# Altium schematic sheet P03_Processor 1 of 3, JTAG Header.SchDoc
size 513 x 386 mm
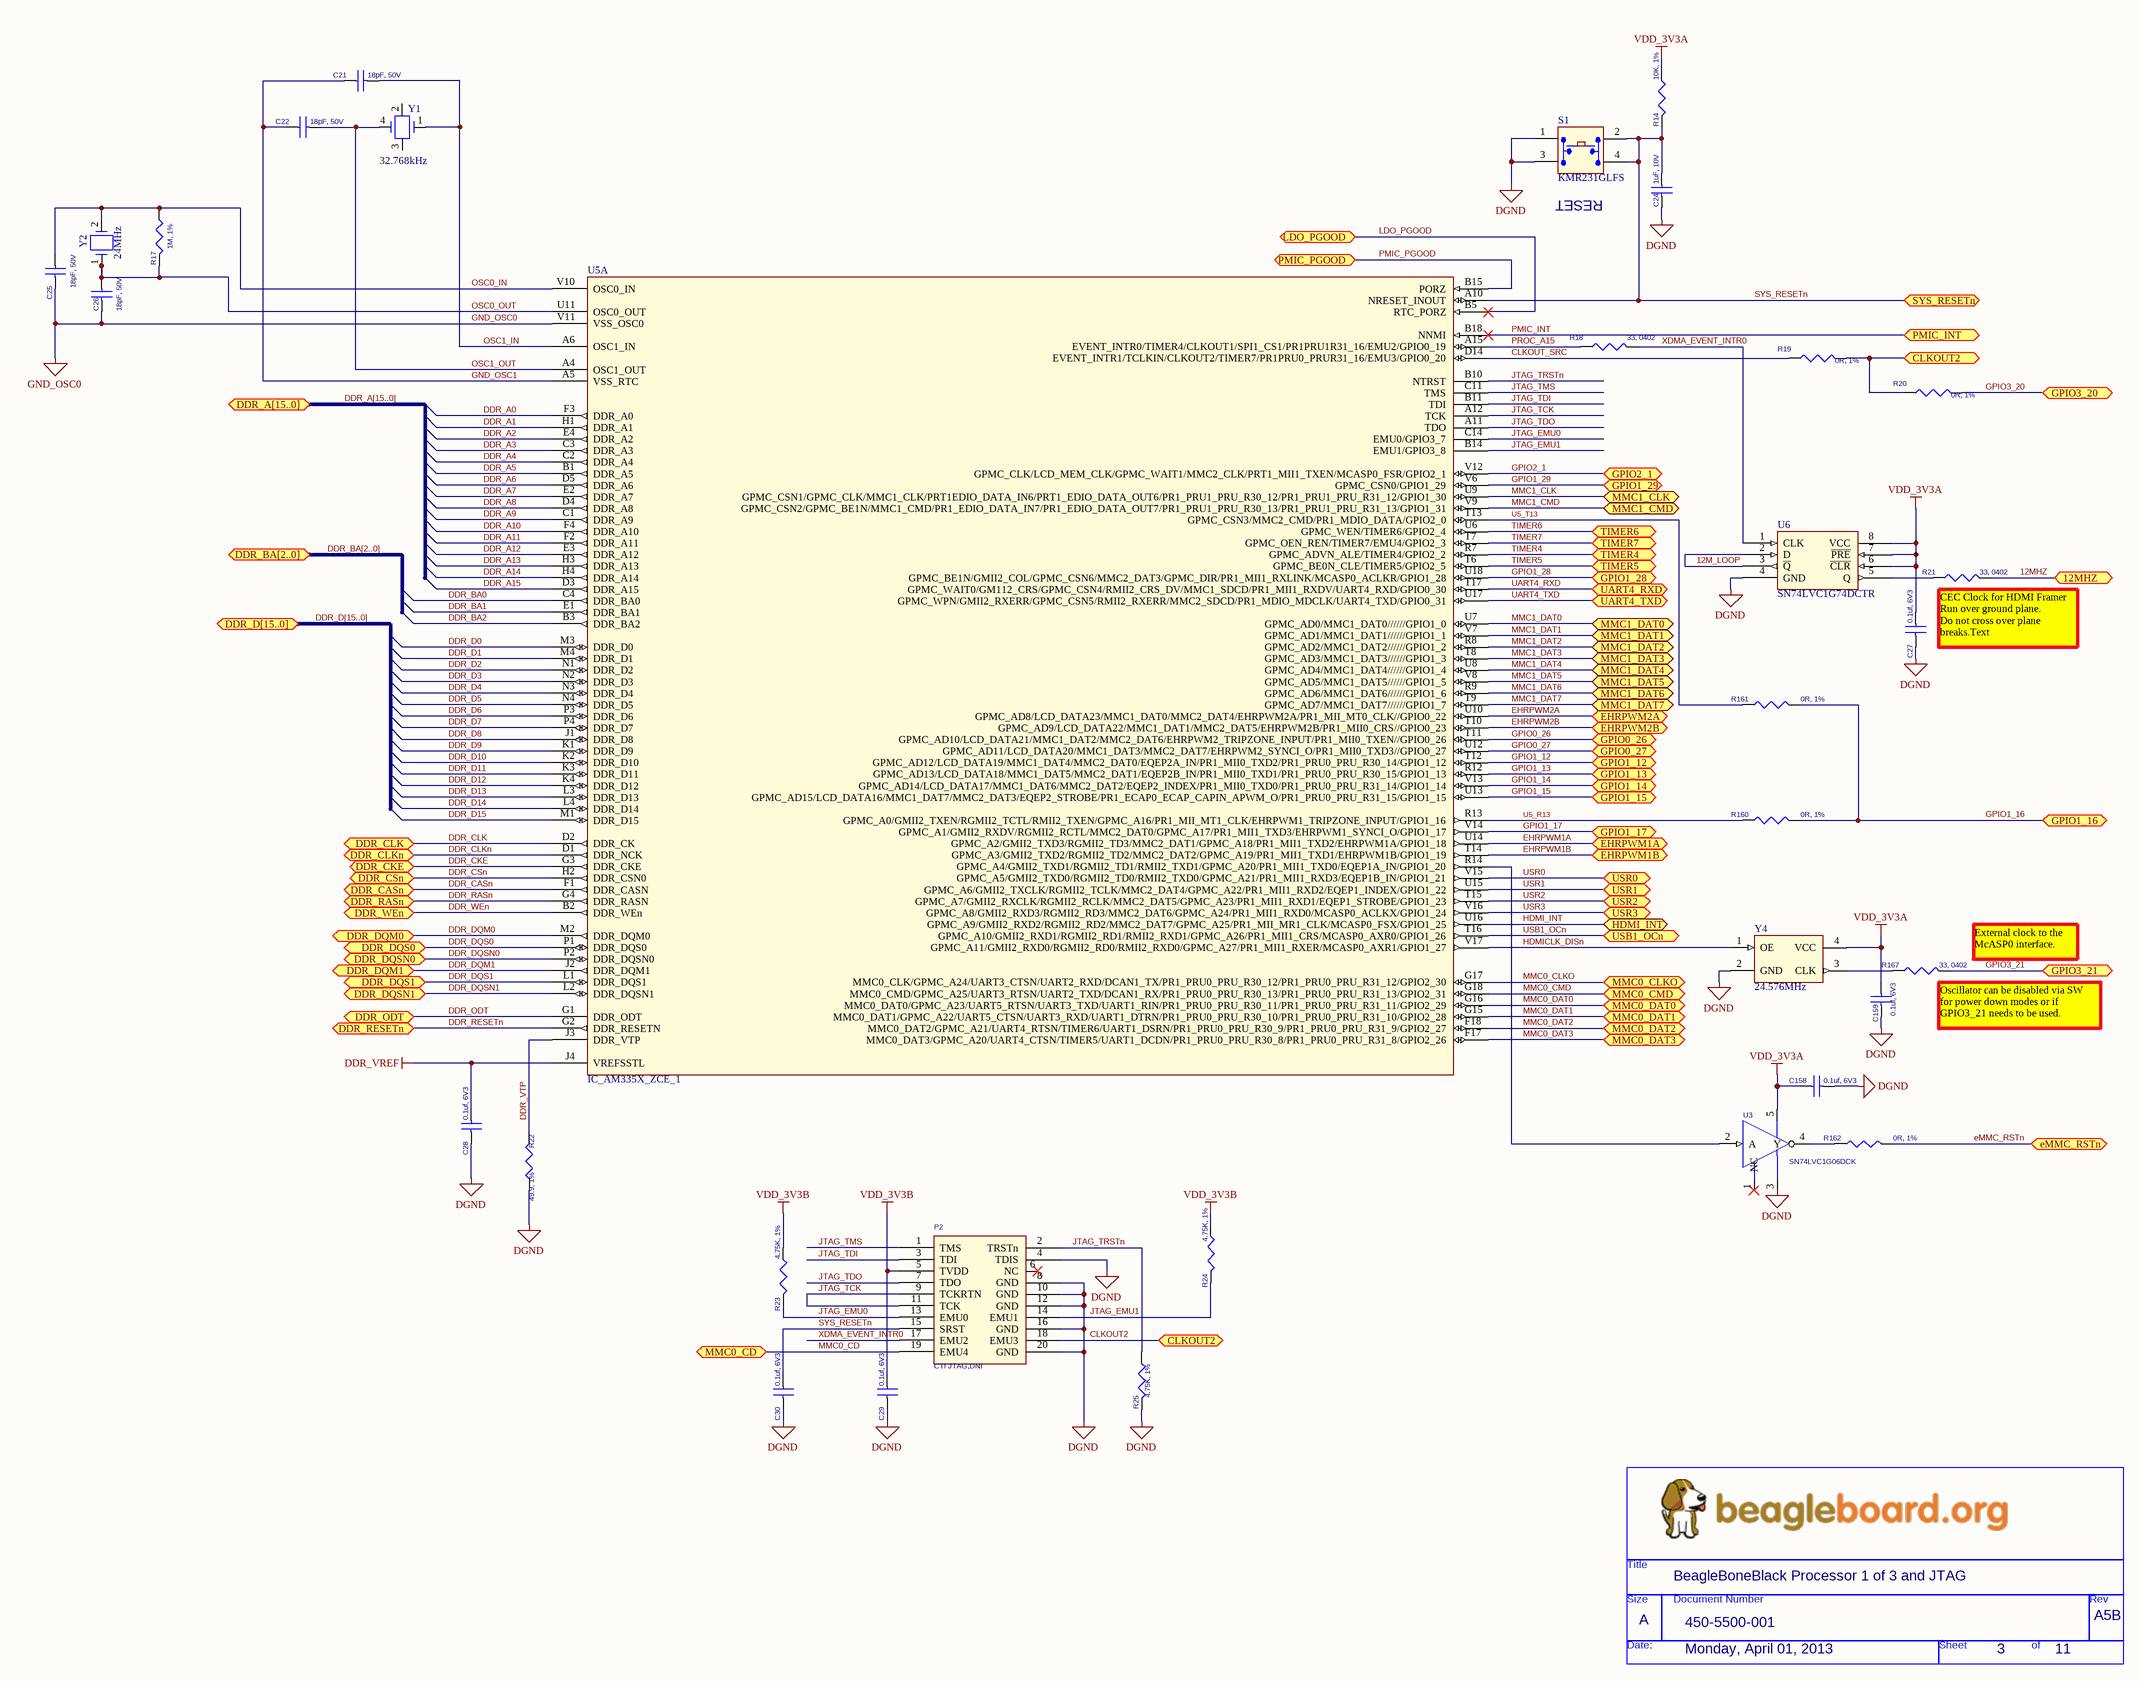
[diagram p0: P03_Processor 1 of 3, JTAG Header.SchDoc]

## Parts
*  Page Create Date: Monday, April 01, 2013  Doc: 450-5500-001  RevCode: A5B  Title: BeagleBoneBlack Processor 1 of 3 and JTAG  Page Size: A  Page Number: 3  Page Count: 11  (hidden comment: BeagleBoard_org)  (graphical)
C21  18pF, 50V  [402]
C22  18pF, 50V  [402]
C24  1uF, 10V  [402]
C25  18pF, 50V  [402]
C26  18pF, 50V  [402]
C27  0.1uf, 6V3  [402]
C28  0.1uf, 6V3  [402]
C29  0.1uf, 6V3  [402]
C30  0.1uf, 6V3  [402]
C158  0.1uf, 6V3  [402]
C159  0.1uf, 6V3  [402]
P2  CTI JTAG,DNI  [HEADER10X2_SMD]
R14  10K, 1%  [402]
R17  1M, 1%  [402]
R18  33, 0402  [402]
R19  0R, 1%  [402]
R20  0R, 1%  [402]
R21  33, 0402  [402]
R22  49.9, 1%  [402]
R23  4.75K, 1%  [402]
R24  4.75K, 1%  [402]
R25  4.75K, 1%  [402]
R160  0R, 1%  [402]
R161  0R, 1%  [402]
R162  0R, 1%  [402]
R167  33, 0402  [402]
S1  KMR231GLFS  [SW4SMD_63X161LS]
U3  SN74LVC1G06DCK  [DCK5_2P15X1P4]
U5  IC_AM335X_ZCE_1  [am33xx_15x15]  (part A of 3)
U6  SN74LVC1G74DCTR  [SOP8_DCT]
Y1  32.768kHz  [XTAL4_126-216SMD]
Y2  24MHz  [XTAL150SMD_125X196]
Y4  24.576MHz  [OSC4_61X65LS_79X98SMD]

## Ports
12MHZ, CLKOUT2, DDR_A[15..0], DDR_BA[2..0], DDR_CASn, DDR_CKE, DDR_CLK, DDR_CLKn, DDR_CSn, DDR_D[15..0], DDR_DQM0, DDR_DQM1, DDR_DQS0, DDR_DQS1, DDR_DQSN0, DDR_DQSN1, DDR_ODT, DDR_RASn, DDR_RESETn, DDR_WEn, EHRPWM1A, EHRPWM1B, EHRPWM2A, EHRPWM2B, eMMC_RSTn, GPIO0_26, GPIO0_27, GPIO1_12, GPIO1_13, GPIO1_14, GPIO1_15, GPIO1_16, GPIO1_17, GPIO1_28, GPIO1_29, GPIO2_1, GPIO3_20, GPIO3_21, HDMI_INT, LDO_PGOOD, MMC0_CD, MMC0_CLKO, MMC0_CMD, MMC0_DAT0, MMC0_DAT1, MMC0_DAT2, MMC0_DAT3, MMC1_CLK, MMC1_CMD, MMC1_DAT0, MMC1_DAT1, MMC1_DAT2, MMC1_DAT3, MMC1_DAT4, MMC1_DAT5, MMC1_DAT6, MMC1_DAT7, PMIC_INT, PMIC_PGOOD, SYS_RESETn, TIMER4, TIMER5, TIMER6, TIMER7, UART4_RXD, UART4_TXD, USB1_OCn, USR0, USR1, USR2, USR3

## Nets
DDR_VREF: C28.1 U5.J4(VREFSSTL)
DGND: C24.2 C27.2 C28.2 C29.2 C30.2 C158.2 C159.2 P2.4(TDIS) P2.8(GND) P2.10(GND) P2.12(GND) P2.16(GND) P2.20(GND) R22.1 R25.2 S1.1(A1) S1.3(A3) U3.3(GND) U6.4(GND) Y4.2(GND)
GND_OSC0: C25.2 C26.2 U5.V11(VSS_OSC0)
VDD_3V3A: C27.1 C158.1 C159.1 R14.1 U3.5(VCC) U6.6(~{CLR}) U6.7(~{PRE}) U6.8(VCC) Y4.4(VCC)
VDD_3V3B: C29.1 P2.5(TVDD) R23.1 R24.1
12M_LOOP: U6.2(D) U6.3(~{Q})
12MHZ: R21.2 ; port 12MHZ
CLKOUT2: P2.18(EMU3) R19.2 R20.1 ; port CLKOUT2
CLKOUT_SRC: R19.1 U5.D14(EVENT_INTR1/TCLKIN/CLKOUT2/TIMER7/PR1PRU0_PRUR31_16/EMU3/GPIO0_20)
DDR_A0: U5.F3(DDR_A0)
DDR_A1: U5.H1(DDR_A1)
DDR_A2: U5.E4(DDR_A2)
DDR_A3: U5.C3(DDR_A3)
DDR_A4: U5.C2(DDR_A4)
DDR_A5: U5.B1(DDR_A5)
DDR_A6: U5.D5(DDR_A6)
DDR_A7: U5.E2(DDR_A7)
DDR_A8: U5.D4(DDR_A8)
DDR_A9: U5.C1(DDR_A9)
DDR_A10: U5.F4(DDR_A10)
DDR_A11: U5.F2(DDR_A11)
DDR_A12: U5.E3(DDR_A12)
DDR_A13: U5.H3(DDR_A13)
DDR_A14: U5.H4(DDR_A14)
DDR_A15: U5.D3(DDR_A15)
DDR_BA0: U5.C4(DDR_BA0)
DDR_BA1: U5.E1(DDR_BA1)
DDR_BA2: U5.B3(DDR_BA2)
DDR_CASn: U5.F1(DDR_CASN) ; port DDR_CASn
DDR_CKE: U5.G3(DDR_CKE) ; port DDR_CKE
DDR_CLK: U5.D2(DDR_CK) ; port DDR_CLK
DDR_CLKn: U5.D1(DDR_NCK) ; port DDR_CLKn
DDR_CSn: U5.H2(DDR_CSN0) ; port DDR_CSn
DDR_D0: U5.M3(DDR_D0)
DDR_D1: U5.M4(DDR_D1)
DDR_D2: U5.N1(DDR_D2)
DDR_D3: U5.N2(DDR_D3)
DDR_D4: U5.N3(DDR_D4)
DDR_D5: U5.N4(DDR_D5)
DDR_D6: U5.P3(DDR_D6)
DDR_D7: U5.P4(DDR_D7)
DDR_D8: U5.J1(DDR_D8)
DDR_D9: U5.K1(DDR_D9)
DDR_D10: U5.K2(DDR_D10)
DDR_D11: U5.K3(DDR_D11)
DDR_D12: U5.K4(DDR_D12)
DDR_D13: U5.L3(DDR_D13)
DDR_D14: U5.L4(DDR_D14)
DDR_D15: U5.M1(DDR_D15)
DDR_DQM0: U5.M2(DDR_DQM0) ; port DDR_DQM0
DDR_DQM1: U5.J2(DDR_DQM1) ; port DDR_DQM1
DDR_DQS0: U5.P1(DDR_DQS0) ; port DDR_DQS0
DDR_DQS1: U5.L1(DDR_DQS1) ; port DDR_DQS1
DDR_DQSN0: U5.P2(DDR_DQSN0) ; port DDR_DQSN0
DDR_DQSN1: U5.L2(DDR_DQSN1) ; port DDR_DQSN1
DDR_ODT: U5.G1(DDR_ODT) ; port DDR_ODT
DDR_RASn: U5.G4(DDR_RASN) ; port DDR_RASn
DDR_RESETn: U5.G2(DDR_RESETN) ; port DDR_RESETn
DDR_VTP: R22.2 U5.J3(DDR_VTP)
DDR_WEn: U5.B2(DDR_WEn) ; port DDR_WEn
EHRPWM1A: U5.U14(GPMC_A2/GMII2_TXD3/RGMII2_TD3/MMC2_DAT1/GPMC_A18/PR1_MII1_TXD2/EHRPWM1A/GPIO1_18) ; port EHRPWM1A
EHRPWM1B: U5.T14(GPMC_A3/GMII2_TXD2/RGMII2_TD2/MMC2_DAT2/GPMC_A19/PR1_MII1_TXD1/EHRPWM1B/GPIO1_19) ; port EHRPWM1B
EHRPWM2A: U5.U10(GPMC_AD8/LCD_DATA23/MMC1_DAT0/MMC2_DAT4/EHRPWM2A/PR1_MII_MT0_CLK//GPIO0_22) ; port EHRPWM2A
EHRPWM2B: U5.T10(GPMC_AD9/LCD_DATA22/MMC1_DAT1/MMC2_DAT5/EHRPWM2B/PR1_MII0_CRS//GPIO0_23) ; port EHRPWM2B
eMMC_RSTn: R162.2 ; port eMMC_RSTn
GND_OSC1: C21.1 C22.1 U5.A5(VSS_RTC)
GPIO0_26: U5.T11(GPMC_AD10/LCD_DATA21/MMC1_DAT2/MMC2_DAT6/EHRPWM2_TRIPZONE_INPUT/PR1_MII0_TXEN//GPIO0_26) ; port GPIO0_26
GPIO0_27: U5.U12(GPMC_AD11/LCD_DATA20/MMC1_DAT3/MMC2_DAT7/EHRPWM2_SYNCI_O/PR1_MII0_TXD3//GPIO0_27) ; port GPIO0_27
GPIO1_12: U5.T12(GPMC_AD12/LCD_DATA19/MMC1_DAT4/MMC2_DAT0/EQEP2A_IN/PR1_MII0_TXD2/PR1_PRU0_PRU_R30_14/GPIO1_12) ; port GPIO1_12
GPIO1_13: U5.R12(GPMC_AD13/LCD_DATA18/MMC1_DAT5/MMC2_DAT1/EQEP2B_IN/PR1_MII0_TXD1/PR1_PRU0_PRU_R30_15/GPIO1_13) ; port GPIO1_13
GPIO1_14: U5.V13(GPMC_AD14/LCD_DATA17/MMC1_DAT6/MMC2_DAT2/EQEP2_INDEX/PR1_MII0_TXD0/PR1_PRU0_PRU_R31_14/GPIO1_14) ; port GPIO1_14
GPIO1_15: U5.U13(GPMC_AD15/LCD_DATA16/MMC1_DAT7/MMC2_DAT3/EQEP2_STROBE/PR1_ECAP0_ECAP_CAPIN_APWM_O/PR1_PRU0_PRU_R31_15/GPIO1_15) ; port GPIO1_15
GPIO1_16: R160.2 R161.2 ; port GPIO1_16
GPIO1_17: U5.V14(GPMC_A1/GMII2_RXDV/RGMII2_RCTL/MMC2_DAT0/GPMC_A17/PR1_MII1_TXD3/EHRPWM1_SYNCI_O/GPIO1_17) ; port GPIO1_17
GPIO1_28: U5.U18(GPMC_BE1N/GMII2_COL/GPMC_CSN6/MMC2_DAT3/GPMC_DIR/PR1_MII1_RXLINK/MCASP0_ACLKR/GPIO1_28) ; port GPIO1_28
GPIO1_29: U5.V6(GPMC_CSN0/GPIO1_29) ; port GPIO1_29
GPIO2_1: U5.V12(GPMC_CLK/LCD_MEM_CLK/GPMC_WAIT1/MMC2_CLK/PRT1_MII1_TXEN/MCASP0_FSR/GPIO2_1) ; port GPIO2_1
GPIO3_20: R20.2 ; port GPIO3_20
GPIO3_21: R167.2 ; port GPIO3_21
HDMI_INT: U5.U16(GPMC_A9/GMII2_RXD2/RGMII2_RD2/MMC2_DAT7/GPMC_A25/PR1_MII_MR1_CLK/MCASP0_FSX/GPIO1_25) ; port HDMI_INT
HDMICLK_DISn: U5.V17(GPMC_A11/GMII2_RXD0/RGMII2_RD0/RMII2_RXD0/GPMC_A27/PR1_MII1_RXER/MCASP0_AXR1/GPIO1_27) Y4.1(OE)
JTAG_EMU0: P2.13(EMU0) R23.2 U5.C14(EMU0/GPIO3_7)
JTAG_EMU1: P2.14(EMU1) R24.2 U5.B14(EMU1/GPIO3_8)
JTAG_TCK: P2.9(TCKRTN) P2.11(TCK) U5.A12(TCK)
JTAG_TDI: P2.3(TDI) U5.B11(TDI)
JTAG_TDO: P2.7(TDO) U5.A11(TDO)
JTAG_TMS: P2.1(TMS) U5.C11(TMS)
JTAG_TRSTn: P2.2(TRSTn) R25.1 U5.B10(NTRST)
LDO_PGOOD: U5.B5(RTC_PORZ) ; port LDO_PGOOD
MMC0_CD: P2.19(EMU4) ; port MMC0_CD
MMC0_CLKO: U5.G17(MMC0_CLK/GPMC_A24/UART3_CTSN/UART2_RXD/DCAN1_TX/PR1_PRU0_PRU_R30_12/PR1_PRU0_PRU_R31_12/GPIO2_30) ; port MMC0_CLKO
MMC0_CMD: U5.G18(MMC0_CMD/GPMC_A25/UART3_RTSN/UART2_TXD/DCAN1_RX/PR1_PRU0_PRU_R30_13/PR1_PRU0_PRU_R31_13/GPIO2_31) ; port MMC0_CMD
MMC0_DAT0: U5.G16(MMC0_DAT0/GPMC_A23/UART5_RTSN/UART3_TXD/UART1_RIN/PR1_PRU0_PRU_R30_11/PR1_PRU0_PRU_R31_11/GPIO2_29) ; port MMC0_DAT0
MMC0_DAT1: U5.G15(MMC0_DAT1/GPMC_A22/UART5_CTSN/UART3_RXD/UART1_DTRN/PR1_PRU0_PRU_R30_10/PR1_PRU0_PRU_R31_10/GPIO2_28) ; port MMC0_DAT1
MMC0_DAT2: U5.F18(MMC0_DAT2/GPMC_A21/UART4_RTSN/TIMER6/UART1_DSRN/PR1_PRU0_PRU_R30_9/PR1_PRU0_PRU_R31_9/GPIO2_27) ; port MMC0_DAT2
MMC0_DAT3: U5.F17(MMC0_DAT3/GPMC_A20/UART4_CTSN/TIMER5/UART1_DCDN/PR1_PRU0_PRU_R30_8/PR1_PRU0_PRU_R31_8/GPIO2_26) ; port MMC0_DAT3
MMC1_CLK: U5.U9(GPMC_CSN1/GPMC_CLK/MMC1_CLK/PRT1EDIO_DATA_IN6/PRT1_EDIO_DATA_OUT6/PR1_PRU1_PRU_R30_12/PR1_PRU1_PRU_R31_12/GPIO1_30) ; port MMC1_CLK
MMC1_CMD: U5.V9(GPMC_CSN2/GPMC_BE1N/MMC1_CMD/PR1_EDIO_DATA_IN7/PR1_EDIO_DATA_OUT7/PR1_PRU1_PRU_R30_13/PR1_PRU1_PRU_R31_13/GPIO1_31) ; port MMC1_CMD
MMC1_DAT0: U5.U7(GPMC_AD0/MMC1_DAT0//////GPIO1_0) ; port MMC1_DAT0
MMC1_DAT1: U5.V7(GPMC_AD1/MMC1_DAT1//////GPIO1_1) ; port MMC1_DAT1
MMC1_DAT2: U5.R8(GPMC_AD2/MMC1_DAT2//////GPIO1_2) ; port MMC1_DAT2
MMC1_DAT3: U5.T8(GPMC_AD3/MMC1_DAT3//////GPIO1_3) ; port MMC1_DAT3
MMC1_DAT4: U5.U8(GPMC_AD4/MMC1_DAT4//////GPIO1_4) ; port MMC1_DAT4
MMC1_DAT5: U5.V8(GPMC_AD5/MMC1_DAT5//////GPIO1_5) ; port MMC1_DAT5
MMC1_DAT6: U5.R9(GPMC_AD6/MMC1_DAT6//////GPIO1_6) ; port MMC1_DAT6
MMC1_DAT7: U5.T9(GPMC_AD7/MMC1_DAT7//////GPIO1_7) ; port MMC1_DAT7
OSC0_IN: C25.1 R17.1 U5.V10(OSC0_IN) Y2.2
OSC0_OUT: C26.1 R17.2 U5.U11(OSC0_OUT) Y2.1
OSC1_IN: C21.2 U5.A6(OSC1_IN) Y1.1
OSC1_OUT: C22.2 U5.A4(OSC1_OUT) Y1.4
PMIC_INT: U5.B18(NNMI) ; port PMIC_INT
PMIC_PGOOD: U5.B15(PORZ) ; port PMIC_PGOOD
PROC_A15: R18.1 U5.A15(EVENT_INTR0/TIMER4/CLKOUT1/SPI1_CS1/PR1PRU1R31_16/EMU2/GPIO0_19)
SYS_RESETn: C24.1 C30.1 P2.15(SRST) R14.2 S1.2(A2) S1.4 U5.A10(NRESET_INOUT) ; port SYS_RESETn
TIMER4: U5.R7(GPMC_ADVN_ALE/TIMER4/GPIO2_2) ; port TIMER4
TIMER5: U5.T6(GPMC_BE0N_CLE/TIMER5/GPIO2_5) ; port TIMER5
TIMER6: U5.U6(GPMC_WEN/TIMER6/GPIO2_4) ; port TIMER6
TIMER7: U5.T7(GPMC_OEN_REN/TIMER7/EMU4/GPIO2_3) ; port TIMER7
U5_R13: R160.1 U5.R13(GPMC_A0/GMII2_TXEN/RGMII2_TCTL/RMII2_TXEN/GPMC_A16/PR1_MII_MT1_CLK/EHRPWM1_TRIPZONE_INPUT/GPIO1_16)
U5_T13: R161.1 U5.T13(GPMC_CSN3/MMC2_CMD/PR1_MDIO_DATA/GPIO2_0)
UART4_RXD: U5.T17(GPMC_WAIT0/GM112_CRS/GPMC_CSN4/RMII2_CRS_DV/MMC1_SDCD/PR1_MII1_RXDV/UART4_RXD/GPIO0_30) ; port UART4_RXD
UART4_TXD: U5.U17(GPMC_WPN/GMII2_RXERR/GPMC_CSN5/RMII2_RXERR/MMC2_SDCD/PR1_MDIO_MDCLK/UART4_TXD/GPIO0_31) ; port UART4_TXD
USB1_OCn: U5.T16(GPMC_A10/GMII2_RXD1/RGMII2_RD1/RMII2_RXD1/GPMC_A26/PR1_MII1_CRS/MCASP0_AXR0/GPIO1_26) ; port USB1_OCn
USR0: U5.V15(GPMC_A5/GMII2_TXD0/RGMII2_TD0/RMII2_TXD0/GPMC_A21/PR1_MII1_RXD3/EQEP1B_IN/GPIO1_21) ; port USR0
USR1: U5.U15(GPMC_A6/GMII2_TXCLK/RGMII2_TCLK/MMC2_DAT4/GPMC_A22/PR1_MII1_RXD2/EQEP1_INDEX/GPIO1_22) ; port USR1
USR2: U5.T15(GPMC_A7/GMII2_RXCLK/RGMII2_RCLK/MMC2_DAT5/GPMC_A23/PR1_MII1_RXD1/EQEP1_STROBE/GPIO1_23) ; port USR2
USR3: U5.V16(GPMC_A8/GMII2_RXD3/RGMII2_RD3/MMC2_DAT6/GPMC_A24/PR1_MII1_RXD0/MCASP0_ACLKX/GPIO1_24) ; port USR3
XDMA_EVENT_INTR0: P2.17(EMU2) R18.2 U6.1(CLK)
NetR21_1: R21.1 U6.5(Q)
NetR162_1: R162.1 U3.4(Y)
NetR167_1: R167.1 Y4.3(CLK)
NetU3_2: U3.2(A) U5.R14(GPMC_A4/GMII2_TXD1/RGMII2_TD1/RMII2_TXD1/GPMC_A20/PR1_MII1_TXD0/EQEP1A_IN/GPIO1_20)

Not connected (* = marked no-connect by the designer): P2 6(NC)*; U3 1(NC)*; Y1 2 3

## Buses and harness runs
bus DDR_A[15..0] = port DDR_A[15..0]
bus DDR_BA[2..0] = port DDR_BA[2..0]
bus DDR_D[15..0] = port DDR_D[15..0]

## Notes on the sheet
- (near S1) RESET
- (near R21) CEC Clock for HDMI Framer
  Run over ground plane.
  Do not cross over plane
  breaks.Text
- (near R167) External clock to the
  McASP0 interface.
- (near R167) Oscillator can be disabled via SW
  for power down modes or if
  GPIO3_21 needs to be used.

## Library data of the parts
C21 C22 C25 C26 = CAP_18PF_COG_50V_5%_0402: CAP CER 18PF 50V 5% NP0 0402; Manufacturer: TDK Corporation; Manufacturer Part Number: C1005C0G1H180J050BA; Temperature Coefficient: C0G, NP0
C24 = CAP_1.0UF_X5R_10V_10%_0402: CAP CER 1UF 10V 10% X5R 0402; Manufacturer: AVX Corporation; Manufacturer Part Number: 0402ZD105KAT2A; Capacitance: 1.0µF
C27-C30 C158 C159 = CAP_0.1uF_X7R_16V_10% 0402: CAP CER 0.1UF 6.3V 10% X5R 0402; Manufacturer: TDK Corporation; Manufacturer Part Number: C1005X5R0J104K050BA; Capacitance: 0.1µF
P2 = HDR_10x2_CJTAG: Dual Line Header 10x2pin Tin; Manufacturer: Samtec Inc; Manufacturer Part Number: FTR-110-03-G-D-06; Connector Type: Unshrouded; Number of Positions: 20; Number of Positions Loaded: 19; Pitch: 0.050" (1.27mm); Row Spacing: 0.100" (2.54mm)
R14 = RES_10K_1/16W_1%_0402: RES 10K OHM 1/16W 5% 0402 SMD; Manufacturer: Rohm Semiconductor; Manufacturer Part Number: MCR01MZPJ103; Power (Watts): 0.063W, 1/16W; Temperature Coefficient: ±200ppm/°C
R17 = RES_1M_1/16W_1%_0402: Resistor 1Mohm 1/16W 1% 0402; Manufacturer: Stackpole Electronics Inc; Manufacturer Part Number: RMCF0402FT1M00; Power (Watts): 0.063W, 1/16W; Temperature Coefficient: ±100ppm/°C
R18 R21 R167 = RES_33_0402: RES 33 OHM 1/16W 5% 0402 SMD; Manufacturer: Panasonic Electronic Components; Manufacturer Part Number: ERJ-2GEJ330X; Resistance (Ohms): 33; Power (Watts): 0.1W, 1/10W; Temperature Coefficient: ±200ppm/°C
R19 R20 R160-R162 = RES_0_1/16W_1%_0402: RES 0.0 OHM 1/16W 0402 SMD; Manufacturer: Yageo; Manufacturer Part Number: RC0402JR-070RL; Resistance (Ohms): 0.0; Power (Watts): 0.063W, 1/16W; Tolerance: Jumper
R22 = RES_4.7K_0402: RES 49.9 OHM 1/16W 1% 0402 SMD; Manufacturer: Yageo; Manufacturer Part Number: RC0402FR-0749R9L; Resistance (Ohms): 49.9; Power (Watts): 0.063W, 1/16W; Temperature Coefficient: ±100ppm/°C
R23-R25 = RES_4.7K_0402: RES 4.75K 1/16W 1% 0402 SMD; Manufacturer: Stackpole Electronics Inc; Manufacturer Part Number: RMCF0402FT4K75; Power (Watts): 0.063W, 1/16W; Temperature Coefficient: ±100ppm/°C
S1 = KMR2: Microminiature Tact Switch for SMT; Manufacturer: C&K Components; Circuit: SPST-NO; Switch Function: Off-Mom; Contact Rating @ Voltage: 0.05A @ 32VDC; Actuator Type: Standard; Actuator Height off PCB, from Pins: 1.90mm; Actuator Orientation: Top Actuated; Outline: 4.60mm x 2.80mm; Illumination: Non-Illuminated; Operating Force: 300gf; Switch Travel: 0.25mm; Mechanical Life: 150,000 Cycles
U3 = SN74LVC1G06DCK: IC INVERTER SINGLE 1INPUT SC705; Manufacturer: Texas Instruments; Manufacturer Part Number: SN74LVC1G06DCKTG4; Logic Type: Inverter, Buffer; Number of Circuits: 1; Voltage - Supply: 1.65 V ~ 5.5 V; Current - Quiescent (Max): 10µA; Current - Output High, Low: -, 32mA; Logic Level - Low: 0.7 V ~ 0.8 V; Logic Level - High: 1.7 V ~ 2 V; Max Propagation Delay @ V, Max CL: 3ns @ 5V, 50pF
U5 = IC_AM335X_ZCE_1: SubArctic Cortex A8 Processor 15x15; Manufacturer: Texas Instruments; Manufacturer Part Number: XAM3359ZCZ; Processor Type: ARM Microprocessor; Voltage: 1.06 V ~ 1.15 V
U6 = SN74LVC1G74DCTR: SINGLE  POSITIVE-EDGE-TRIGGERED  D-TYPE  FLIP-FLOP WITH  CLEAR  AND  PRESET; Manufacturer: Texas Instruments; Function: Set(Preset) and Reset; Output Type: Differential; Number of Elements: 1; Frequency - Clock: 200MHz; Delay Time - Propagation: 1.6ns; Trigger Type: Positive Edge; Current - Output High, Low: 32mA, 32mA; Voltage - Supply: 1.65 V ~ 5.5 V
Y1 = CRYS_32_768KHz_SMD32: CRYSTAL 32.768KHZ 12.5PF SMD; Manufacturer: Citizen Finetech Miyota; Manufacturer Part Number: CM200C-32.768KAZF-UT; Frequency Tolerance: ±30ppm; ESR (Equivalent Series Resistance): 50 kOhm; Operating Mode: Fundamental
Y2 = CRYS_24MHz_SCC: CRYSTAL 24.000MHZ 18PF SMD; Manufacturer: TXC CORPORATION; Manufacturer Part Number: 7A-24.000MAAJ-T; Frequency Stability: ±30ppm; ESR (Equivalent Series Resistance): 50 Ohm; Operating Mode: Fundamental
Y4 = ASDMB: Manufacturer: Abracon Corporation; Manufacturer Part Number: ASDMB-24.576MHZ-LC-T; Function: Standby (Power Down); Output: CMOS; Voltage - Supply: 1.8 V ~ 3.3 V; Frequency Stability: ±50ppm; Current - Supply (Max): 16mA; Current - Supply (Disable) (Max): 15µA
